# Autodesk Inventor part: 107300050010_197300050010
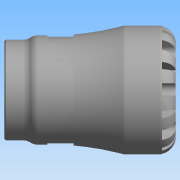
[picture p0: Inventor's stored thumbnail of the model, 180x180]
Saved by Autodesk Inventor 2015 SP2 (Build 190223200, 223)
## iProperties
Created: 2016-12
Part Number: 107300050010_197300050010
Material: Generic
Description: PLASSON FEMALE INTEGRAL BRASS THREAD 50-1" SERIES 1
Document SubType Name: Modeling
Designer: KIM
Density: 1 g/cm^3
Appearance: Default
Author: KIM
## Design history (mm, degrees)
derived "1073.ipt"
feature "Solid1::1073.ipt"
tag "TaggingFeature1"
body "Solid1"
other parameters: "d0" = 113, "d1" = 34.02, "d3" = 62.5, "d4" = 85, "d6" = 81, "d8" = 72.25, "d13" = 9, "d14" = 9, "d15" = 0, "d17" = 360 deg, "d19" = 8 deg, "d20" = 1, "d21" = 1, "d22" = 8 deg, "d24" = 0, "d26" = 360 deg, "d32" = 8.5, "d33" = 8.5, "d39" = 0.90873, "d42" = 30.291, "d43" = 66.3, "d46" = 4.16667, "d47" = 19, "d48" = 28.77645, "d50" = 4.29, "d51" = 0.85, "d54" = 17.5, "d55" = 11, "d57" = 17.64, "d58" = 0, "d68" = 360 deg, "d72" = 1, "d74" = 0, "d76" = 14.875, "E_" = 85, "H_" = 113, "l_" = 81, "G_" = 30.291, "l_2" = 19, "d9" = 11.25, "d11" = 85, "d12" = 62.5, "d49" = 13
